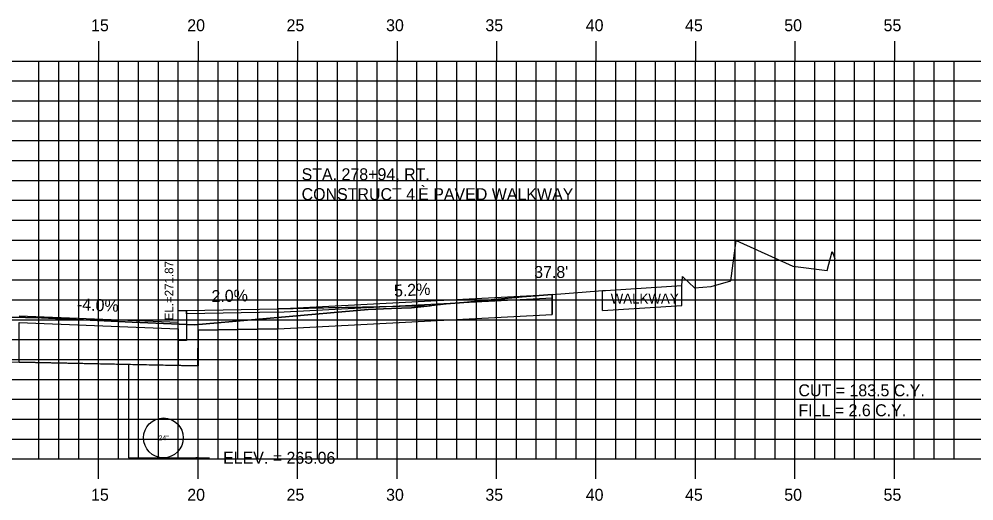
# Model space of a CAD drawing. Extents: x 854676 to 854846, y 366268 to 366378.
# Drawn here: x 854770.11 to 854818.1, y 366323.02 to 366347.24 of the extents above; entities that cross this region are included whole.
import ezdxf

# ---------------------------------------------------------------- set-up
doc = ezdxf.new("R2010")
doc.units = 0
for name, color, linetype in [('ANNOTATION', 7, 'Continuous'), ('D_Curb_Type_1_Rt', 7, 'Continuous'), ('D_Roadway_Edge_Shoulder', 7, 'Continuous'), ('D_Roadway_FinishedGrade', 7, 'Continuous'), ('D_Roadway_Sidewalks_Paved', 7, 'Continuous'), ('D_Roadway_SubGrade', 7, 'Continuous'), ('D_Text_Monospaced', 7, 'Continuous'), ('D_Text_Standard', 7, 'Continuous'), ('H_V ANNOTATION', 7, 'Continuous'), ('JUNK COM EXC', 7, 'Continuous'), ('JUNK FILL', 7, 'Continuous'), ('junk strct exc', 7, 'Continuous'), ('MAJOR', 7, 'Continuous'), ('MINOR', 7, 'Continuous'), ('PDRAIN', 7, 'Continuous'), ('S_Roadway_Centerline', 7, 'Continuous')]:
    doc.layers.add(name, color=color, linetype=linetype)

msp = doc.modelspace()

# ---------------------------------------------------------------- linework, layer by layer
at = {"layer": 'D_Curb_Type_1_Rt'}
for points in [[(854778.523, 366332.586), (854778.523, 366331.086), (854778.107, 366331.086), (854778.107, 366332.586)], [(854778.526, 366332.585), (854778.526, 366331.085), (854778.109, 366331.085), (854778.109, 366332.585)]]:
    msp.add_lwpolyline(points, close=True, dxfattribs=at)
at = {"layer": 'D_Roadway_Edge_Shoulder'}
msp.add_line((854770.11, 366332.322), (854778.107, 366332.002), dxfattribs=at)
at = {"layer": 'D_Roadway_FinishedGrade'}
msp.add_line((854783.115, 366332.677), (854790.806, 366332.834), dxfattribs=at)
at = {"layer": 'D_Roadway_Sidewalks_Paved'}
for p, q in [((854783.115, 366332.677), (854796.903, 366333.394)), ((854783.106, 366332.51), (854796.903, 366333.228))]:
    msp.add_line(p, q, dxfattribs=at)
msp.add_lwpolyline([(854778.526, 366332.585), (854783.115, 366332.677), (854783.115, 366332.51), (854778.526, 366332.418)], close=True, dxfattribs=at)
at = {"layer": 'D_Roadway_SubGrade'}
for p in [(854796.903, 366333.394), (854783.115, 366331.676)]:
    msp.add_line(p, (854796.903, 366332.394), dxfattribs=at)
for points in [[(854783.115, 366332.51), (854783.115, 366331.676), (854779.11, 366331.596), (854779.11, 366329.808), (854778.11, 366329.828)], [(854748.106, 366330.145), (854756.919, 366330.198), (854759.089, 366330.208), (854770.11, 366329.988)]]:
    msp.add_lwpolyline(points, dxfattribs=at)
msp.add_lwpolyline([(854770.11, 366331.988), (854778.11, 366331.668), (854778.11, 366329.828), (854770.11, 366329.988)], close=True, dxfattribs=at)
at = {"layer": 'D_Text_Standard'}
msp.add_lwpolyline([(854779.11, 366325.188), (854778.999, 366325.188), (854779.679, 366325.188)], dxfattribs=at)
at = {"layer": 'JUNK COM EXC'}
for points in [[(854783.115, 366332.235), (854783.115, 366331.676), (854796.903, 366332.394), (854796.903, 366333.394), (854795.396, 366333.272), (854793.998, 366333.142), (854792.993, 366333.048), (854792.457, 366332.999), (854791.582, 366332.919), (854789.835, 366332.726), (854788.831, 366332.697), (854788.422, 366332.675), (854787.652, 366332.637), (854783.115, 366332.235), (854783.115, 366332.235)], [(854759.089, 366330.208), (854770.11, 366329.988), (854779.099, 366329.809), (854779.11, 366331.596), (854783.115, 366331.676), (854783.115, 366332.235)], [(854783.115, 366332.235), (854778.945, 366331.865), (854775.789, 366331.999), (854771.23, 366332.218), (854765.539, 366332.337)]]:
    msp.add_lwpolyline(points, dxfattribs=at)
at = {"layer": 'JUNK FILL'}
msp.add_lwpolyline([(854783.106, 366332.677), (854783.106, 366332.234), (854787.652, 366332.637), (854788.422, 366332.675), (854788.831, 366332.697), (854789.835, 366332.726), (854790.778, 366332.83), (854783.115, 366332.677)], close=True, dxfattribs=at)
at = {"layer": 'junk strct exc'}
msp.add_lwpolyline([(854775.61, 366329.878), (854775.61, 366325.188), (854779.11, 366325.188), (854779.11, 366329.808)], close=True, dxfattribs=at)
at = {"layer": 'MAJOR'}
for p, q in [((854774.106, 366346.13), (854774.106, 366345.128)), ((854779.106, 366346.13), (854779.106, 366345.128)), ((854784.106, 366346.13), (854784.106, 366345.128)), ((854789.106, 366346.13), (854789.106, 366345.128)), ((854794.106, 366346.13), (854794.106, 366345.128)), ((854799.106, 366346.13), (854799.106, 366345.128)), ((854804.106, 366346.13), (854804.106, 366345.128)), ((854809.106, 366346.13), (854809.106, 366345.128)), ((854814.106, 366346.13), (854814.106, 366345.128)), ((854689.106, 366345.128), (854829.106, 366345.128)), ((854689.106, 366345.128), (854829.106, 366345.128)), ((854774.106, 366325.128), (854774.106, 366345.128)), ((854779.106, 366325.128), (854779.106, 366345.128)), ((854784.106, 366325.128), (854784.106, 366345.128)), ((854789.106, 366325.128), (854789.106, 366345.128)), ((854794.106, 366325.128), (854794.106, 366345.128)), ((854799.106, 366325.128), (854799.106, 366345.128)), ((854804.106, 366325.128), (854804.106, 366345.128)), ((854809.106, 366325.128), (854809.106, 366345.128)), ((854814.106, 366325.128), (854814.106, 366345.128)), ((854689.106, 366340.128), (854829.106, 366340.128)), ((854689.106, 366335.128), (854829.106, 366335.128)), ((854689.106, 366330.128), (854829.106, 366330.128)), ((854689.106, 366325.128), (854829.106, 366325.128)), ((854689.106, 366325.128), (854829.106, 366325.128)), ((854774.106, 366324.126), (854774.106, 366325.128)), ((854779.106, 366324.126), (854779.106, 366325.128)), ((854784.106, 366324.126), (854784.106, 366325.128)), ((854789.106, 366324.126), (854789.106, 366325.128)), ((854794.106, 366324.126), (854794.106, 366325.128)), ((854799.106, 366324.126), (854799.106, 366325.128)), ((854804.106, 366324.126), (854804.106, 366325.128)), ((854809.106, 366324.126), (854809.106, 366325.128)), ((854814.106, 366324.126), (854814.106, 366325.128))]:
    msp.add_line(p, q, dxfattribs=at)
at = {"layer": 'MINOR'}
for p, q in [((854771.106, 366325.128), (854771.106, 366345.128)), ((854772.106, 366325.128), (854772.106, 366345.128)), ((854773.106, 366325.128), (854773.106, 366345.128)), ((854775.106, 366325.128), (854775.106, 366345.128)), ((854776.106, 366325.128), (854776.106, 366345.128)), ((854777.106, 366325.128), (854777.106, 366345.128)), ((854778.106, 366325.128), (854778.106, 366345.128)), ((854780.106, 366325.128), (854780.106, 366345.128)), ((854781.106, 366325.128), (854781.106, 366345.128)), ((854782.106, 366325.128), (854782.106, 366345.128)), ((854783.106, 366325.128), (854783.106, 366345.128)), ((854785.106, 366325.128), (854785.106, 366345.128)), ((854786.106, 366325.128), (854786.106, 366345.128)), ((854787.106, 366325.128), (854787.106, 366345.128)), ((854788.106, 366325.128), (854788.106, 366345.128)), ((854790.106, 366325.128), (854790.106, 366345.128)), ((854791.106, 366325.128), (854791.106, 366345.128)), ((854792.106, 366325.128), (854792.106, 366345.128)), ((854793.106, 366325.128), (854793.106, 366345.128)), ((854795.106, 366325.128), (854795.106, 366345.128)), ((854796.106, 366325.128), (854796.106, 366345.128)), ((854797.106, 366325.128), (854797.106, 366345.128)), ((854798.106, 366325.128), (854798.106, 366345.128)), ((854800.106, 366325.128), (854800.106, 366345.128)), ((854801.106, 366325.128), (854801.106, 366345.128)), ((854802.106, 366325.128), (854802.106, 366345.128)), ((854803.106, 366325.128), (854803.106, 366345.128)), ((854805.106, 366325.128), (854805.106, 366345.128)), ((854806.106, 366325.128), (854806.106, 366345.128)), ((854807.106, 366325.128), (854807.106, 366345.128)), ((854808.106, 366325.128), (854808.106, 366345.128)), ((854810.106, 366325.128), (854810.106, 366345.128)), ((854811.106, 366325.128), (854811.106, 366345.128)), ((854812.106, 366325.128), (854812.106, 366345.128)), ((854813.106, 366325.128), (854813.106, 366345.128)), ((854815.106, 366325.128), (854815.106, 366345.128)), ((854816.106, 366325.128), (854816.106, 366345.128)), ((854817.106, 366325.128), (854817.106, 366345.128)), ((854689.106, 366344.128), (854829.106, 366344.128)), ((854689.106, 366343.128), (854829.106, 366343.128)), ((854689.106, 366342.128), (854829.106, 366342.128)), ((854689.106, 366341.128), (854829.106, 366341.128)), ((854689.106, 366339.128), (854829.106, 366339.128)), ((854689.106, 366338.128), (854829.106, 366338.128)), ((854689.106, 366337.128), (854829.106, 366337.128)), ((854689.106, 366336.128), (854829.106, 366336.128)), ((854689.106, 366334.128), (854829.106, 366334.128)), ((854689.106, 366333.128), (854829.106, 366333.128)), ((854689.106, 366332.128), (854829.106, 366332.128)), ((854689.106, 366331.128), (854829.106, 366331.128)), ((854689.106, 366329.128), (854829.106, 366329.128)), ((854689.106, 366328.128), (854829.106, 366328.128)), ((854689.106, 366327.128), (854829.106, 366327.128)), ((854689.106, 366326.128), (854829.106, 366326.128))]:
    msp.add_line(p, q, dxfattribs=at)
at = {"layer": 'PDRAIN'}
msp.add_lwpolyline([(854775.61, 366329.878), (854775.61, 366325.188), (854779.11, 366325.188), (854779.11, 366329.808)], dxfattribs=at)
msp.add_circle((854777.36, 366326.188), 1, dxfattribs=at)
at = {"layer": 'S_Roadway_Centerline'}
for p, q in [((854803.427, 366332.846), (854803.427, 366333.849)), ((854799.437, 366332.587), (854799.437, 366333.591))]:
    msp.add_line(p, q, dxfattribs=at)
for points in [[(854765.539, 366332.337), (854771.23, 366332.218), (854775.789, 366331.999), (854778.945, 366331.865), (854787.652, 366332.637), (854788.422, 366332.675), (854788.831, 366332.697), (854789.835, 366332.726), (854791.582, 366332.919), (854792.457, 366332.999), (854792.993, 366333.048), (854793.998, 366333.142), (854795.396, 366333.272), (854798.41, 366333.516), (854799.437, 366333.591), (854799.582, 366333.598), (854803.427, 366333.849), (854803.456, 366334.28), (854803.461, 366334.296), (854803.491, 366334.267), (854804.063, 366333.732), (854804.902, 366333.795), (854805.883, 366334.086), (854806.151, 366336.112), (854808.999, 366334.822), (854810.727, 366334.597), (854810.971, 366335.563), (854811.109, 366335.205)], [(854799.437, 366332.587), (854803.427, 366332.846)]]:
    msp.add_lwpolyline(points, dxfattribs=at)

# ---------------------------------------------------------------- texts
at = {"layer": 'ANNOTATION'}
for s, p in [('STA. 278+94, RT.', (854784.308, 366339.139)), ("CONSTRUCT 4'È PAVED WALKWAY", (854784.308, 366338.139)), ('CUT = 183.5 C.Y.', (854809.283, 366328.278)), ('FILL = 2.6 C.Y.', (854809.283, 366327.276))]:
    msp.add_text(s, height=0.6, dxfattribs=at).set_placement(p)
for s, rotation, p in [('5.2%', 2.9784, (854788.967, 366333.282)), ('2.0%', 1.1485, (854779.783, 366333.01)), ('-4.0%', 357.7093, (854773.004, 366332.607))]:
    msp.add_text(s, height=0.6, rotation=rotation, dxfattribs=at).set_placement(p)
at = {"layer": 'D_Text_Monospaced'}
msp.add_text('WALKWAY', height=0.5, dxfattribs=at).set_placement((854799.845, 366332.939))
at = {"layer": 'D_Text_Standard'}
msp.add_text(' EL.=271.87', height=0.4335, rotation=90, dxfattribs=at).set_placement((854777.861, 366331.933))
for s, p in [("37.8'", (854795.998, 366334.226)), ('ELEV. = 265.06', (854780.359, 366324.888))]:
    msp.add_text(s, height=0.6, dxfattribs=at).set_placement(p)
at = {"layer": 'H_V ANNOTATION'}
for s, p in [('15', (854773.724, 366346.628)), ('20', (854778.56, 366346.628)), ('25', (854783.552, 366346.628)), ('30', (854788.555, 366346.628)), ('35', (854793.547, 366346.628)), ('40', (854798.592, 366346.628)), ('45', (854803.584, 366346.628)), ('50', (854808.571, 366346.628)), ('55', (854813.563, 366346.628)), ('15', (854773.724, 366323.028)), ('20', (854778.56, 366323.028)), ('25', (854783.552, 366323.028)), ('30', (854788.555, 366323.028)), ('35', (854793.547, 366323.028)), ('40', (854798.592, 366323.028)), ('45', (854803.584, 366323.028)), ('50', (854808.571, 366323.028)), ('55', (854813.563, 366323.028))]:
    msp.add_text(s, height=0.6, dxfattribs=at).set_placement(p)
at = {"layer": 'PDRAIN'}
msp.add_text('24"', height=0.25, dxfattribs=at).set_placement((854777.118, 366326.063))

doc.saveas('drawing.dxf')
